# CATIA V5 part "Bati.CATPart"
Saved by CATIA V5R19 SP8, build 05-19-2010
Part number: Bati
Bounding box of the stored display mesh (mm): x -450 to 0, y -1400 to 2850, z -149.807 to 3749.807
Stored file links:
  C:\Users\ThinkMotion\Desktop\EU_thinkMotion\iao\IAO_MMS_Groupe3\fovide\fovide\Bati.CATPart
  C:\Users\ThinkMotion\Desktop\EU_thinkMotion\iao\IAO_MMS_Groupe3\fovide\fovide\fovide.CATProduct
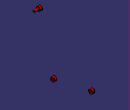
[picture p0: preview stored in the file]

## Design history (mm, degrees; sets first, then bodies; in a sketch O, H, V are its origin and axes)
External parameters (linked from other documents)
  `External.Diamètre bielle` = 150 mm
  `External.Rayon bielle` = 75 mm
Set1
  Plane1: linked copy from another document
  Point1 "Point.E": linked copy from another document
  Plane2: linked copy from another document
  Point2 "Point.A": linked copy from another document
  Line1: linked copy from another document
  Plane3: linked copy from another document
  Point3 "Point.D": linked copy from another document
  Line2: linked copy from another document
Body1 (main body)
  Sketch1 on Plane1, origin (-300, 0, 0), H (0, 1, 0), V (0, 0, 1)
    circle A1 centre (-1250, 3600) radius 150
    point P1 (-1250, 3600)
    reference projected point E1 (-1250, 3600) from Point1
    radius A1 = 150 {= `External.Diamètre bielle`}
    coincidence: P1 E1
  Pad1: profile Sketch1, direction (-1, 0, 0), length 150 {= `External.Diamètre bielle`}
  Sketch2 on Plane1, origin (-300, 0, 0), H (0, 1, 0), V (0, 0, 1)
    circle A1 centre (-1250, 3600) radius 75
    point P1 (-1250, 3600)
    reference projected point E1 (-1250, 3600) from Point1
    radius A1 = 75 {= `External.Rayon bielle`}
    coincidence: P1 E1
  Pad2: profile Sketch2, direction (1, 0, 0), length 300 {= `External.Diamètre bielle` *2}
  Sketch3 on Plane2, origin (-75, 0, 0), H (0, 1, 0), V (0, 0, 1)
    circle A1 centre (2700, 600) radius 150
    point P1 (2700, 600)
    reference projected point E1 (2700, 600) from Point2
    radius A1 = 150 {= `External.Diamètre bielle`}
    coincidence: P1 E1
  Pad3: profile Sketch3, direction (-1, 0, 0), length 150 {= `External.Diamètre bielle`}
  Sketch4 on start face of Pad3, origin (-75, 2700, 600), H (0, 1, 0), V (0, 0, 1)
    point P1 (0, 0)
    intersected point E1 (0, 0) from Line1
    coincidence: E1 P1
  Hole1: placed by Sketch4, at (-75, 2700, 600) direction (-1, 0, 0), diameter 150 {= `External.Diamètre bielle`}, through (limit type 6)
  Sketch5 on Plane3, origin (-75, 0, 0), H (0, 1, 0), V (0, 0, 1)
    circle A1 centre (0, 0) radius 150
    point P1 (0, 0)
    reference projected point E1 (0, 0) from Point3
    radius A1 = 150 {= `External.Diamètre bielle`}
    coincidence: P1 E1
  Pad4: profile Sketch5, direction (-1, 0, 0), length 150 {= `External.Diamètre bielle`}
  Sketch6 on start face of Pad4, origin (-75, 0, 0), H (0, 1, 0), V (0, 0, 1)
    point P1 (0, 0)
    intersected point E1 (0, 0) from Line2
    coincidence: E1 P1
  Hole2: placed by Sketch6, at (-75, 0, 0) direction (-1, 0, 0), diameter 150 {= `External.Diamètre bielle`}, through (limit type 6)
